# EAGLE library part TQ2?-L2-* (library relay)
LOW PROFILE 2 FORM C RELAY NAiS 2 coil latching Source: http://www.mew-europe.com/.. en_ds_61020_0001.pdf Source: http://www.mew-europe.com/.. en_ds_61020_0002.pdf
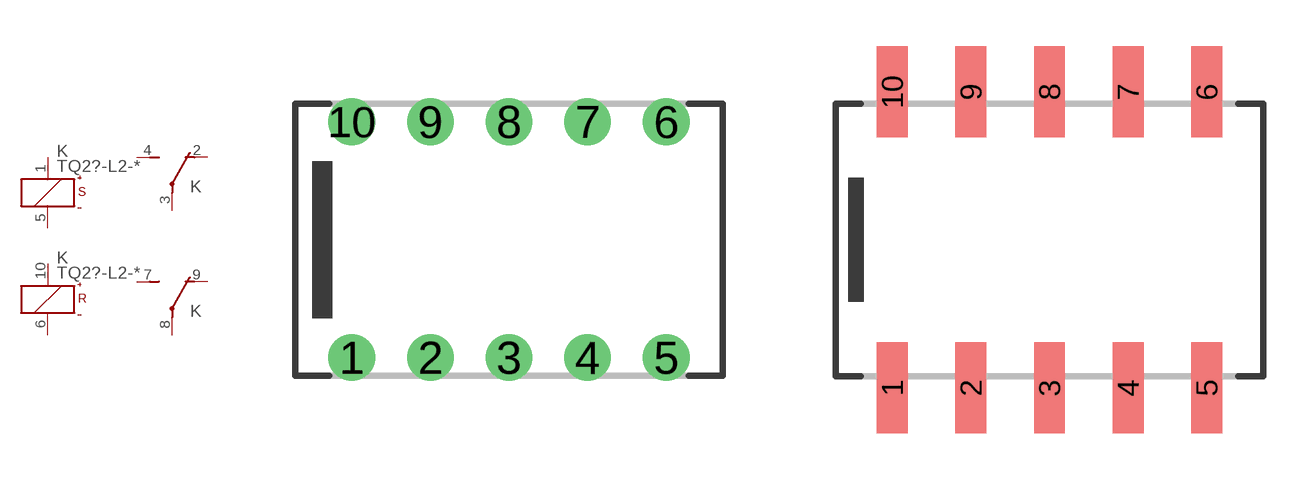
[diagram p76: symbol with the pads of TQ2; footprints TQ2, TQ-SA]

Designator prefix K; gates S=K+-S R=K+-R 1=U 2=U

## TQ2-L2- (MF: AROMAT/ MATSUSHITA; MPN: TQ2-L2-9V; OC_FARNELL: 1217662; OC_NEWARK: 64K3196)  [TQ2]
1  S:+  pas
2  1:O  pas
3  1:P  pas
4  1:S  pas
5  S:-  pas
6  R:-  pas
7  2:S  pas
8  2:P  pas
9  2:O  pas
10  R:+  pas

## TQ2SA-L2-1.5V (OC_FARNELL: unknown; OC_NEWARK: unknown), TQ2SA-L2-3V (MPN: TQ2SA-L2-3V; OC_FARNELL: unknown; OC_NEWARK: 15P9786), TQ2SA-L2-4.5V (MPN: TQ2SA-L2-4.5V; OC_FARNELL: unknown; OC_NEWARK: 15P9788), TQ2SA-L2-5V (MF: AROMAT/ MATSUSHITA; MPN: TQ2SA-L2-5V; OC_FARNELL: 625760; OC_NEWARK: 64K3202), TQ2SA-L2-6V (OC_FARNELL: unknown; OC_NEWARK: unknown), TQ2SA-L2-9V (OC_FARNELL: unknown; OC_NEWARK: unknown), TQ2SA-L2-12V (MPN: TQ2SA-L2-12V; OC_FARNELL: 1124058; OC_NEWARK: 02M6304), TQ2SA-L2-24V (MF: FARNELL; MPN: TQ2SA-L2-24V; OC_FARNELL: 625784; OC_NEWARK: 15J0011)  [TQ-SA]
Pads as for TQ2

## TQ2SL-L2-1.5V (OC_FARNELL: unknown; OC_NEWARK: unknown), TQ2SL-L2-3V (MF: AROMAT/ MATSUSHITA; MPN: TQ2SL-L2-3V-Z; OC_FARNELL: unknown; OC_NEWARK: 10C9899), TQ2SL-L2-4.5V (MPN: TQ2SL-L2-4.5V; OC_FARNELL: unknown; OC_NEWARK: 15P9795), TQ2SL-L2-5V (MPN: TQ2SL-L2-5V; OC_FARNELL: unknown; OC_NEWARK: 15P9796), TQ2SL-L2-6V (OC_FARNELL: unknown; OC_NEWARK: unknown), TQ2SL-L2-9V (OC_FARNELL: unknown; OC_NEWARK: unknown), TQ2SL-L2-12V (OC_FARNELL: unknown; OC_NEWARK: unknown), TQ2SL-L2-24V (MPN: TQ2SL-L2-24V; OC_FARNELL: unknown; OC_NEWARK: 15P9794)  [TQ-SL]
Pads as for TQ2

## TQ2SS-L2-1.5V (OC_FARNELL: unknown; OC_NEWARK: unknown), TQ2SS-L2-3V (MPN: TQ2SS-L2-3V; OC_FARNELL: unknown; OC_NEWARK: 15P9802), TQ2SS-L2-4.5V (MPN: TQ2SS-L2-4.5V-Z; OC_FARNELL: unknown; OC_NEWARK: 15P9803), TQ2SS-L2-5V (MF: AROMAT/ MATSUSHITA; MPN: TQ2SS-L2-5V; OC_FARNELL: unknown; OC_NEWARK: 64K3206), TQ2SS-L2-6V (OC_FARNELL: unknown; OC_NEWARK: unknown), TQ2SS-L2-9V (OC_FARNELL: unknown; OC_NEWARK: unknown), TQ2SS-L2-12V (MPN: TQ2SS-L2-12V; OC_FARNELL: unknown; OC_NEWARK: 15P9800), TQ2SS-L2-24V (MPN: TQ2SS-L2-24V; OC_FARNELL: unknown; OC_NEWARK: 15P9801)  [TQ-SS]
Pads as for TQ2

## Footprint TQ2 (pad centres in mm)
LOW PROFILE 2 FORM C RELAY NAiS Source: http://www.mew-europe.com/.. en_ds_61020_0001.pdf
drill 1 round: 1 -5.08,-3.81; 2 -2.54,-3.81; 3 0,-3.81; 4 2.54,-3.81; 5 5.08,-3.81; 6 5.08,3.81; 7 2.54,3.81; 8 0,3.81; 9 -2.54,3.81; 10 -5.08,3.81

## Footprint TQ-SA (pad centres in mm)
LOW-PROFILE TQ-SMD RELAYS NAiS Source: http://www.mew-europe.com/.. en_ds_61021_0004.pdf
smd 1 x 2.94: 1 -5.08,-4.78; 2 -2.54,-4.78; 3 0,-4.78; 4 2.54,-4.78; 5 5.08,-4.78; 6 5.08,4.78; 7 2.54,4.78; 8 0,4.78; 9 -2.54,4.78; 10 -5.08,4.78

## Footprint TQ-SL (pad centres in mm)
LOW-PROFILE TQ-SMD RELAYS NAiS Source: http://www.mew-europe.com/.. en_ds_61021_0004.pdf
smd 1 x 2.94: 1 -5.08,-4.78; 2 -2.54,-4.78; 3 0,-4.78; 4 2.54,-4.78; 5 5.08,-4.78; 6 5.08,4.78; 7 2.54,4.78; 8 0,4.78; 9 -2.54,4.78; 10 -5.08,4.78

## Footprint TQ-SS (pad centres in mm)
LOW-PROFILE TQ-SMD RELAYS NAiS Source: http://www.mew-europe.com/.. en_ds_61021_0004.pdf
smd 1 x 1.84: 1 -5.08,-4.23; 2 -2.54,-4.23; 3 0,-4.23; 4 2.54,-4.23; 5 5.08,-4.23; 6 5.08,4.23; 7 2.54,4.23; 8 0,4.23; 9 -2.54,4.23; 10 -5.08,4.23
